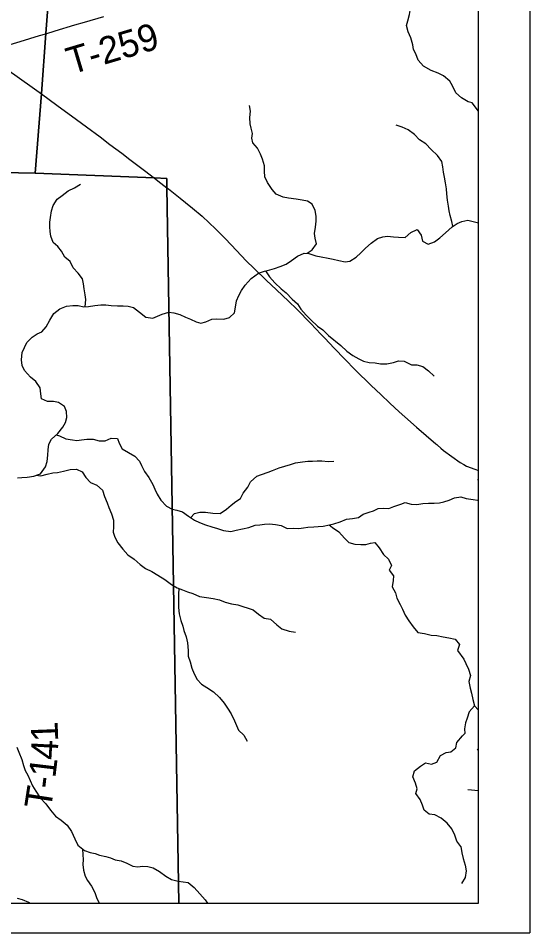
# Model space of a CAD drawing. Extents: x 0 to 34, y 0 to 22.
# Drawn here: x 8.088 to 9.17, y 13.563 to 15.496 of the extents above; entities that cross this region are included whole.
import ezdxf

# ---------------------------------------------------------------- set-up
doc = ezdxf.new("R2010")
doc.units = 0
for name, color, linetype in [('Default', 7, 'Continuous'), ('GM_X_Major_River', 7, 'Continuous'), ('GM_X_Minor_River', 7, 'Continuous'), ('GM_X_State_Route', 7, 'Continuous'), ('GM_X_Township_Road', 7, 'Continuous'), ('GM_X_Township_Road_Text', 7, 'Continuous'), ('SH_Cut_Line', 7, 'Continuous'), ('SH_Data', 7, 'Continuous')]:
    doc.layers.add(name, color=color, linetype=linetype)

msp = doc.modelspace()

# ---------------------------------------------------------------- linework, layer by layer
at = {"layer": 'Default'}
msp.add_lwpolyline([(3.47, 19.2407), (3.2768, 17.1355), (3.2667, 16.919), (3.1974, 16.1596), (3.1343, 15.4291), (3.1796, 15.4266), (4.2078, 15.3826), (4.2393, 15.3805), (4.819, 15.349), (5.5157, 15.319), (7.9465, 15.1727), (8.1234, 15.1688), (8.137, 15.3372), (8.146, 15.4642), (8.2031, 16.209), (8.2895, 16.85), (8.3286, 17.3076), (8.3307, 17.3314), (8.3334, 17.361), (8.3935, 18.0719)], dxfattribs=at)
for points in [[(8.4279, 13.6252), (9.0621, 13.6252), (9.0621, 18.0279), (9.0619, 18.0279), (8.9638, 18.036), (8.3935, 18.0719), (8.3334, 17.361), (8.3307, 17.3314), (8.3286, 17.3076), (8.2895, 16.85), (8.2031, 16.209), (8.146, 15.4642), (8.137, 15.3372), (8.1234, 15.1688), (8.3761, 15.1587), (8.4023, 15.1576), (8.4024, 15.1386)], [(2.9696, 13.6252), (8.4279, 13.6252), (8.4024, 15.1386), (8.4023, 15.1576), (8.3761, 15.1587), (8.1234, 15.1688), (7.9465, 15.1727), (5.5157, 15.319), (4.819, 15.349), (4.2393, 15.3805), (4.2078, 15.3826), (3.1796, 15.4266), (3.1343, 15.4291), (3.0617, 14.6751), (3.0457, 14.4958), (3.0429, 14.4692)]]:
    msp.add_lwpolyline(points, close=True, dxfattribs=at)
at = {"layer": 'GM_X_Major_River'}
msp.add_line((9.0393, 15.0692), (9.0621, 15.064), dxfattribs=at)
for points in [[(8.2269, 14.8865), (8.2367, 14.8866), (8.25, 14.8893), (8.2626, 14.8904), (8.2732, 14.8902), (8.2845, 14.8887), (8.2978, 14.8883), (8.3099, 14.8884), (8.3208, 14.8877), (8.3317, 14.8847), (8.3447, 14.8753), (8.3581, 14.8643), (8.3728, 14.8624), (8.3827, 14.8666), (8.3923, 14.8705), (8.4068, 14.8751), (8.4174, 14.8736), (8.4302, 14.8699), (8.4418, 14.8646), (8.4523, 14.8602), (8.4642, 14.8545), (8.474, 14.852), (8.4847, 14.8547), (8.4977, 14.86), (8.5076, 14.8609), (8.5227, 14.8601), (8.5353, 14.8635), (8.5458, 14.8735), (8.5477, 14.8856), (8.5496, 14.8988), (8.5545, 14.9104), (8.5604, 14.9205), (8.5679, 14.9317), (8.5812, 14.9461), (8.5963, 14.9575), (8.609, 14.9617), (8.6204, 14.9644), (8.63, 14.9675), (8.6422, 14.9717), (8.6548, 14.9767), (8.666, 14.984), (8.6788, 14.9931), (8.693, 14.9995), (8.7032, 14.9993), (8.7178, 14.9939), (8.7291, 14.9917), (8.7435, 14.9894), (8.7544, 14.9872), (8.7664, 14.9842), (8.78, 14.9816), (8.7899, 14.9828), (8.803, 14.9916), (8.8127, 15.0004), (8.8232, 15.01), (8.8349, 15.0206), (8.8485, 15.0309), (8.8595, 15.0344), (8.8694, 15.0356), (8.8823, 15.0345), (8.8925, 15.0335), (8.9065, 15.0331), (8.9185, 15.0437), (8.9323, 15.0498), (8.9407, 15.0378), (8.9437, 15.0248), (8.9553, 15.0188), (8.9691, 15.0238), (8.9799, 15.0318), (8.9924, 15.0425), (9.006, 15.0554), (9.0172, 15.0626), (9.0268, 15.0669), (9.0393, 15.0692)], [(8.0862, 14.5247), (8.0957, 14.5252), (8.1067, 14.526), (8.1208, 14.5283), (8.1353, 14.5328), (8.1456, 14.5477), (8.1489, 14.559), (8.1508, 14.5726), (8.1511, 14.584), (8.1526, 14.5957), (8.1582, 14.6062), (8.1715, 14.6183), (8.1824, 14.6317), (8.188, 14.6418), (8.1906, 14.6519), (8.1898, 14.6652), (8.186, 14.6752), (8.1733, 14.6839), (8.1624, 14.6861), (8.1495, 14.6861), (8.1372, 14.6917), (8.136, 14.702), (8.1341, 14.7153), (8.1254, 14.7285), (8.1135, 14.7375), (8.101, 14.7519), (8.096, 14.7623), (8.0945, 14.7745), (8.0964, 14.7896), (8.1009, 14.8001), (8.1061, 14.8109), (8.1174, 14.8224), (8.1279, 14.8289), (8.1375, 14.8336), (8.1472, 14.8439), (8.1545, 14.8582), (8.1632, 14.872), (8.176, 14.8822), (8.1902, 14.8879), (8.2035, 14.8894), (8.2148, 14.8891), (8.2269, 14.8865)]]:
    msp.add_lwpolyline(points, dxfattribs=at)
at = {"layer": 'GM_X_Minor_River'}
msp.add_line((9.0621, 15.2997), (9.0487, 15.3175), dxfattribs=at)
for points in [[(9.0487, 15.3175), (9.0402, 15.3195), (9.026, 15.3282), (9.0141, 15.339), (9.0072, 15.3532), (9.001, 15.3632), (8.9876, 15.3744), (8.9767, 15.3803), (8.9621, 15.3859), (8.9456, 15.3954), (8.9345, 15.4077), (8.9294, 15.4211), (8.9243, 15.4307), (8.923, 15.4402), (8.9188, 15.4547), (8.9133, 15.4677), (8.9095, 15.4811), (8.9123, 15.4909), (8.916, 15.5041), (8.9178, 15.5169)], [(8.6995, 14.9994), (8.7103, 15.0066), (8.7189, 15.0197), (8.7161, 15.0315), (8.7152, 15.0414), (8.7173, 15.055), (8.7184, 15.0672), (8.7182, 15.0778), (8.7165, 15.0896), (8.71, 15.103), (8.6999, 15.1096), (8.689, 15.1118), (8.6761, 15.1139), (8.6599, 15.1161), (8.6489, 15.1182), (8.6339, 15.1246), (8.625, 15.1343), (8.6155, 15.1489), (8.61, 15.1611), (8.6088, 15.1733), (8.6094, 15.1846), (8.6047, 15.1984), (8.6004, 15.2091), (8.5942, 15.2217), (8.5846, 15.2329), (8.5825, 15.2428), (8.5835, 15.2527), (8.5807, 15.2637), (8.579, 15.2733), (8.5778, 15.2866), (8.5795, 15.2998), (8.5775, 15.312)], [(9.008, 15.0567), (9.0059, 15.0664), (9.002, 15.0794), (8.9999, 15.0889), (8.9986, 15.0988), (8.9966, 15.1121), (8.995, 15.1254), (8.9944, 15.1357), (8.9924, 15.1482), (8.99, 15.1604), (8.9876, 15.1707), (8.9863, 15.1825), (8.9846, 15.1932), (8.9754, 15.2062), (8.962, 15.219), (8.9505, 15.231), (8.9371, 15.2396), (8.9263, 15.2505), (8.9133, 15.2602), (8.9001, 15.2662), (8.8881, 15.2706)], [(8.2297, 14.8865), (8.2308, 14.9015), (8.2295, 14.9114), (8.2275, 14.924), (8.2258, 14.9346), (8.2237, 14.9453), (8.2149, 14.9572), (8.2038, 14.9688), (8.1976, 14.9819), (8.1868, 14.9912), (8.1795, 15.0042), (8.1717, 15.0139), (8.1621, 15.0224), (8.1566, 15.0358), (8.1553, 15.0453), (8.1548, 15.0555), (8.1546, 15.0654), (8.1559, 15.0753), (8.1585, 15.0889), (8.1618, 15.1006), (8.17, 15.1137), (8.1808, 15.1218), (8.1938, 15.1318), (8.2069, 15.138), (8.2195, 15.1453)], [(8.6114, 14.9622), (8.6197, 14.95), (8.6308, 14.9369), (8.6442, 14.9245), (8.655, 14.9159), (8.6676, 14.9024), (8.6792, 14.8923), (8.6858, 14.8815), (8.6976, 14.8684), (8.7073, 14.8587), (8.7214, 14.8455), (8.7322, 14.8374), (8.7445, 14.8257), (8.7706, 14.8047), (8.7836, 14.7927), (8.7963, 14.7834), (8.809, 14.7763), (8.8187, 14.7715), (8.8308, 14.7687), (8.8433, 14.7676), (8.8546, 14.7655), (8.8679, 14.7656), (8.882, 14.7688), (8.8926, 14.772), (8.9047, 14.7714), (8.9205, 14.7638), (8.9315, 14.7636), (8.9439, 14.76), (8.9562, 14.751), (8.9685, 14.7394)], [(8.1683, 14.6154), (8.1749, 14.6132), (8.1888, 14.6068), (8.2024, 14.6047), (8.2122, 14.6037), (8.2221, 14.605), (8.2331, 14.6063), (8.2467, 14.6061), (8.2592, 14.6032), (8.2716, 14.6029), (8.2846, 14.6087), (8.2979, 14.6077), (8.3018, 14.5978), (8.308, 14.5859), (8.3211, 14.578), (8.335, 14.5706), (8.3446, 14.5601), (8.3486, 14.5506), (8.3548, 14.5379), (8.3644, 14.5256), (8.3728, 14.5103), (8.3768, 14.5007), (8.3819, 14.4903), (8.3899, 14.4773), (8.4014, 14.4645), (8.4134, 14.4582), (8.4232, 14.4565), (8.4356, 14.4525), (8.448, 14.4435), (8.461, 14.4349), (8.4716, 14.4305), (8.4839, 14.4253), (8.4975, 14.4209), (8.5096, 14.4176), (8.5223, 14.4136), (8.5375, 14.4114), (8.5493, 14.4142), (8.5622, 14.417), (8.5759, 14.4197), (8.5892, 14.4244), (8.5991, 14.4253), (8.609, 14.4267), (8.6196, 14.4276), (8.6321, 14.4262), (8.6442, 14.4241), (8.6569, 14.4178), (8.6702, 14.4179), (8.6819, 14.4173), (8.6914, 14.4186), (8.7009, 14.4203), (8.7134, 14.4208), (8.7229, 14.4214), (8.7332, 14.4227), (8.7465, 14.4255), (8.756, 14.4272), (8.7693, 14.4315), (8.7827, 14.4369), (8.7956, 14.4385), (8.8082, 14.4409), (8.8182, 14.4476), (8.8304, 14.4519), (8.8399, 14.4547), (8.8499, 14.4595), (8.862, 14.4604), (8.8722, 14.4598), (8.8825, 14.4637), (8.8974, 14.4688), (8.9069, 14.4724), (8.9194, 14.4691), (8.9315, 14.4681), (8.944, 14.4701), (8.9562, 14.4714), (8.9679, 14.4708), (8.9793, 14.4717), (8.9888, 14.4738), (8.9999, 14.4777), (9.0113, 14.4824), (9.0243, 14.4848), (9.0357, 14.4806)], [(8.4527, 14.4404), (8.4606, 14.449), (8.4724, 14.4518), (8.4845, 14.4523), (8.4996, 14.4501), (8.5151, 14.4494), (8.5286, 14.4586), (8.5382, 14.4668), (8.5482, 14.4745), (8.5586, 14.4812), (8.5641, 14.4924), (8.5735, 14.5051), (8.5798, 14.516), (8.5929, 14.5279), (8.6028, 14.5319), (8.6166, 14.5369), (8.6261, 14.5405), (8.6402, 14.5456), (8.6642, 14.553), (8.6745, 14.5566), (8.6894, 14.5586), (8.7008, 14.5599), (8.711, 14.5601), (8.7205, 14.5607), (8.7303, 14.5608), (8.7439, 14.5594), (8.7561, 14.56)], [(8.1261, 14.53), (8.136, 14.5286), (8.149, 14.5321), (8.1612, 14.5353), (8.171, 14.5359), (8.1836, 14.5387), (8.1977, 14.5425), (8.2109, 14.5427), (8.2233, 14.5371), (8.231, 14.5252), (8.2411, 14.5151), (8.2542, 14.5092), (8.2661, 14.4987), (8.2704, 14.4853), (8.2762, 14.4719), (8.2794, 14.4616), (8.2852, 14.4486), (8.2894, 14.4349), (8.2895, 14.4212), (8.2889, 14.4099), (8.2925, 14.3995), (8.299, 14.3869), (8.309, 14.3738), (8.3201, 14.3618), (8.3336, 14.3528), (8.3458, 14.3412), (8.3574, 14.3326), (8.3705, 14.3263), (8.3833, 14.3188), (8.3982, 14.3094), (8.4124, 14.2989), (8.4244, 14.2918), (8.4353, 14.2875), (8.4462, 14.2834), (8.4571, 14.2798), (8.4718, 14.2738), (8.4861, 14.2717), (8.5008, 14.2698), (8.5137, 14.2669), (8.5261, 14.2618), (8.5396, 14.2581), (8.5528, 14.2559), (8.563, 14.2527), (8.5747, 14.2494), (8.5852, 14.2454), (8.5964, 14.2361), (8.6087, 14.2279), (8.6219, 14.2257), (8.6349, 14.2141), (8.6461, 14.2055), (8.6616, 14.2003), (8.6748, 14.1981)], [(9.0357, 14.4806), (9.0504, 14.4789), (9.0599, 14.4772), (9.0621, 14.4771)], [(8.7462, 14.4254), (8.7528, 14.4196), (8.7663, 14.4103), (8.7781, 14.3968), (8.7878, 14.3882), (8.8006, 14.3846), (8.8127, 14.3836), (8.8233, 14.3834), (8.8332, 14.3862), (8.8427, 14.3879), (8.8516, 14.3767), (8.8611, 14.3625), (8.8712, 14.3528), (8.8781, 14.3394), (8.8726, 14.3296), (8.8818, 14.3177), (8.8816, 14.3075), (8.8794, 14.2942), (8.886, 14.2812), (8.8892, 14.2701), (8.8961, 14.2567), (8.9012, 14.2471), (8.907, 14.2341), (8.9147, 14.2222), (8.9235, 14.2099), (8.9339, 14.1979), (8.9479, 14.1957), (8.9618, 14.1921), (8.9739, 14.1911), (8.9875, 14.1885), (8.9992, 14.186), (9.0124, 14.1835), (9.0216, 14.1723), (9.0176, 14.1595), (9.0307, 14.1414)], [(8.4279, 14.2904), (8.4271, 14.2785), (8.4269, 14.2645), (8.427, 14.2508), (8.4286, 14.2368), (8.4317, 14.2227), (8.436, 14.2112), (8.4381, 14.2017), (8.4431, 14.1883), (8.4463, 14.1757), (8.4474, 14.1597), (8.4476, 14.1476), (8.4515, 14.1358), (8.4554, 14.1224), (8.4601, 14.1105), (8.4663, 14.0983), (8.4759, 14.0886), (8.4868, 14.0816), (8.501, 14.0718), (8.5136, 14.0598), (8.524, 14.0482), (8.5309, 14.0374), (8.5386, 14.0255), (8.5459, 14.011), (8.5499, 14.0006), (8.5542, 13.9911), (8.5654, 13.9802), (8.5727, 13.9676)], [(9.0307, 14.1414), (9.0349, 14.1322), (9.0405, 14.12), (9.0449, 14.107), (9.0417, 14.0942), (9.0442, 14.0801), (9.0471, 14.069), (9.05, 14.0557), (9.0532, 14.0424), (9.0621, 14.0335)], [(9.0532, 14.0424), (9.0424, 14.0296), (9.0381, 14.0167), (9.0342, 14.0069), (9.0325, 13.9936), (9.0332, 13.9841), (9.0284, 13.9789)], [(9.0247, 13.7454), (9.0158, 13.7566), (9.0122, 13.7688), (9.0053, 13.7822), (8.9957, 13.7942), (8.9831, 13.805), (8.9696, 13.8117), (8.9579, 13.8135), (8.9467, 13.8217), (8.9438, 13.8324), (8.9388, 13.8442), (8.9292, 13.8569), (8.932, 13.8667), (8.9285, 13.8793), (8.9231, 13.8923), (8.9268, 13.9048), (8.9391, 13.9148), (8.9495, 13.9222), (8.9627, 13.9193), (8.9741, 13.9232), (8.9816, 13.9375), (8.9939, 13.9437), (9.0037, 13.9454), (9.0141, 13.9535), (9.0163, 13.9652), (9.0284, 13.9789)], [(8.0849, 13.9548), (8.0892, 13.9445), (8.0957, 13.9288), (8.0988, 13.9162), (8.1028, 13.9059), (8.1083, 13.8956), (8.1184, 13.8733), (8.1254, 13.8618), (8.1346, 13.848), (8.1461, 13.8356), (8.1564, 13.8218), (8.1667, 13.8094), (8.1791, 13.8008), (8.1913, 13.79), (8.2006, 13.7769), (8.2078, 13.7616), (8.214, 13.7478), (8.2278, 13.7365), (8.2402, 13.7325), (8.2504, 13.73), (8.2601, 13.7271), (8.2733, 13.7238), (8.2831, 13.7214), (8.2929, 13.717), (8.3057, 13.7148), (8.3178, 13.7097), (8.3305, 13.7037), (8.3407, 13.7024), (8.3506, 13.7033), (8.3619, 13.7031), (8.3736, 13.7002), (8.3867, 13.6924), (8.4002, 13.6826), (8.4121, 13.6756), (8.4261, 13.6719), (8.4367, 13.6705), (8.4472, 13.6688), (8.4599, 13.6583), (8.4725, 13.6451), (8.4832, 13.6324), (8.4885, 13.6252)], [(8.2236, 13.7399), (8.2245, 13.7275), (8.2251, 13.7176), (8.2245, 13.707), (8.2258, 13.6952), (8.2293, 13.6826), (8.2344, 13.673), (8.2433, 13.6611), (8.2502, 13.6476), (8.2538, 13.6373), (8.2595, 13.6252)], [(9.0247, 13.7454), (9.0264, 13.7314), (9.0293, 13.7194), (9.0341, 13.7056), (9.0358, 13.6935), (9.0337, 13.6798), (9.026, 13.6666)], [(8.0855, 13.6361), (8.0961, 13.6329), (8.1096, 13.6277), (8.1129, 13.6252)]]:
    msp.add_lwpolyline(points, dxfattribs=at)
at = {"layer": 'GM_X_State_Route'}
for points in [[(7.9066, 15.5052), (7.925, 15.4915), (7.9444, 15.477), (7.9726, 15.4559), (7.9746, 15.4544), (7.9805, 15.4499), (8.0147, 15.4243), (8.0262, 15.4162), (8.0638, 15.3891), (8.1175, 15.3509), (8.1373, 15.3366)], [(8.1373, 15.3366), (8.1698, 15.313), (8.2114, 15.2825), (8.2324, 15.2669), (8.2613, 15.2455), (8.2821, 15.2298), (8.3068, 15.2109), (8.3242, 15.1978), (8.3549, 15.1745), (8.3764, 15.1581)], [(8.3764, 15.1581), (8.3792, 15.156), (8.3835, 15.1527), (8.4026, 15.138)], [(8.4026, 15.138), (8.4057, 15.1356), (8.4306, 15.116), (8.4417, 15.1071)], [(8.4417, 15.1071), (8.4567, 15.095), (8.4771, 15.0777), (8.4923, 15.0639), (8.5056, 15.0511), (8.5266, 15.0297), (8.5496, 15.0052), (8.5706, 14.9833), (8.5869, 14.9671), (8.6129, 14.9423), (8.6342, 14.9223), (8.6602, 14.8983), (8.6775, 14.8813), (8.7071, 14.8511), (8.7284, 14.8287)], [(8.7284, 14.8287), (8.7366, 14.82), (8.7566, 14.7988), (8.779, 14.7756), (8.8012, 14.7531), (8.8349, 14.72), (8.855, 14.7006), (8.8744, 14.6823), (8.8942, 14.6644), (8.9062, 14.6538)], [(8.9062, 14.6538), (8.9311, 14.6321), (8.9718, 14.5965), (8.9736, 14.595)], [(8.9736, 14.595), (8.9753, 14.5935), (8.9823, 14.5874), (8.9882, 14.5823), (9.0229, 14.5572), (9.0307, 14.5529)], [(9.0307, 14.5529), (9.0367, 14.5496), (9.0545, 14.5428), (9.0621, 14.5405)]]:
    msp.add_lwpolyline(points, dxfattribs=at)
at = {"layer": 'GM_X_Township_Road'}
for p, q in [((9.0599, 14.521), (9.0621, 14.5192)), ((9.0621, 13.9481), (9.0595, 13.9502)), ((9.0394, 13.8659), (9.0621, 13.8632))]:
    msp.add_line(p, q, dxfattribs=at)
for points in [[(8.1462, 15.4637), (8.1658, 15.4696), (8.208, 15.4822), (8.2283, 15.4881), (8.2688, 15.5002)], [(8.0147, 15.4243), (8.0195, 15.4255), (8.0241, 15.4267), (8.028, 15.4278), (8.0382, 15.431), (8.0569, 15.4366), (8.0921, 15.4471), (8.1331, 15.4597), (8.1462, 15.4637)]]:
    msp.add_lwpolyline(points, dxfattribs=at)
at = {"layer": 'SH_Cut_Line'}
msp.add_lwpolyline([(2.9696, 13.6252), (9.0621, 13.6252), (9.0621, 20.4252), (3.5682, 20.4252), (3.5424, 20.1754), (3.5231, 19.8516), (3.5169, 19.7823), (3.5125, 19.7343), (3.5092, 19.6961), (3.5066, 19.6647), (3.4966, 19.5464), (3.4903, 19.4759), (3.4748, 19.2963), (3.47, 19.2407), (3.2768, 17.1355), (3.2667, 16.919), (3.1974, 16.1596), (3.1343, 15.4291), (3.0617, 14.6751), (3.0457, 14.4958), (3.0429, 14.4692)], close=True, dxfattribs=at)
at = {"layer": 'SH_Data'}
for p in [(9.1704, 20.5628), (2.1704, 13.5628)]:
    msp.add_line(p, (9.1704, 13.5628), dxfattribs=at)

# ---------------------------------------------------------------- texts
at = {"layer": 'GM_X_Township_Road_Text'}
for s, height, rotation, p in [('T-259', 0.05682, 16.5932, (8.2, 15.3772)), ('1', 0.0568, 92.2189, (8.1727, 13.9676)), ('4', 0.0568, 86.9217, (8.1708, 13.9272)), ('1', 0.0568, 83.1964, (8.1663, 13.8887)), ('-', 0.0568, 82.9616, (8.1634, 13.8655)), ('T', 0.0568, 81.1848, (8.1567, 13.8217))]:
    msp.add_text(s, height=height, rotation=rotation, dxfattribs=at).set_placement(p)

doc.saveas('drawing.dxf')
